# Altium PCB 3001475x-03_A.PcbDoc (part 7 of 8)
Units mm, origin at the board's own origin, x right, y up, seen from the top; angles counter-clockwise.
Board outline 100 x 72 mm, 12 copper layers (Top Layer, L2 GND, Layer 3, L4 GND, Layer 5, L6 PWR, L7 3V3, Layer 8, L9 GND, Layer 10, L11 GND, Bottom Layer), stack 1.735 mm thick; 428 components, 499 nets, 1973 pads, 1473 vias.
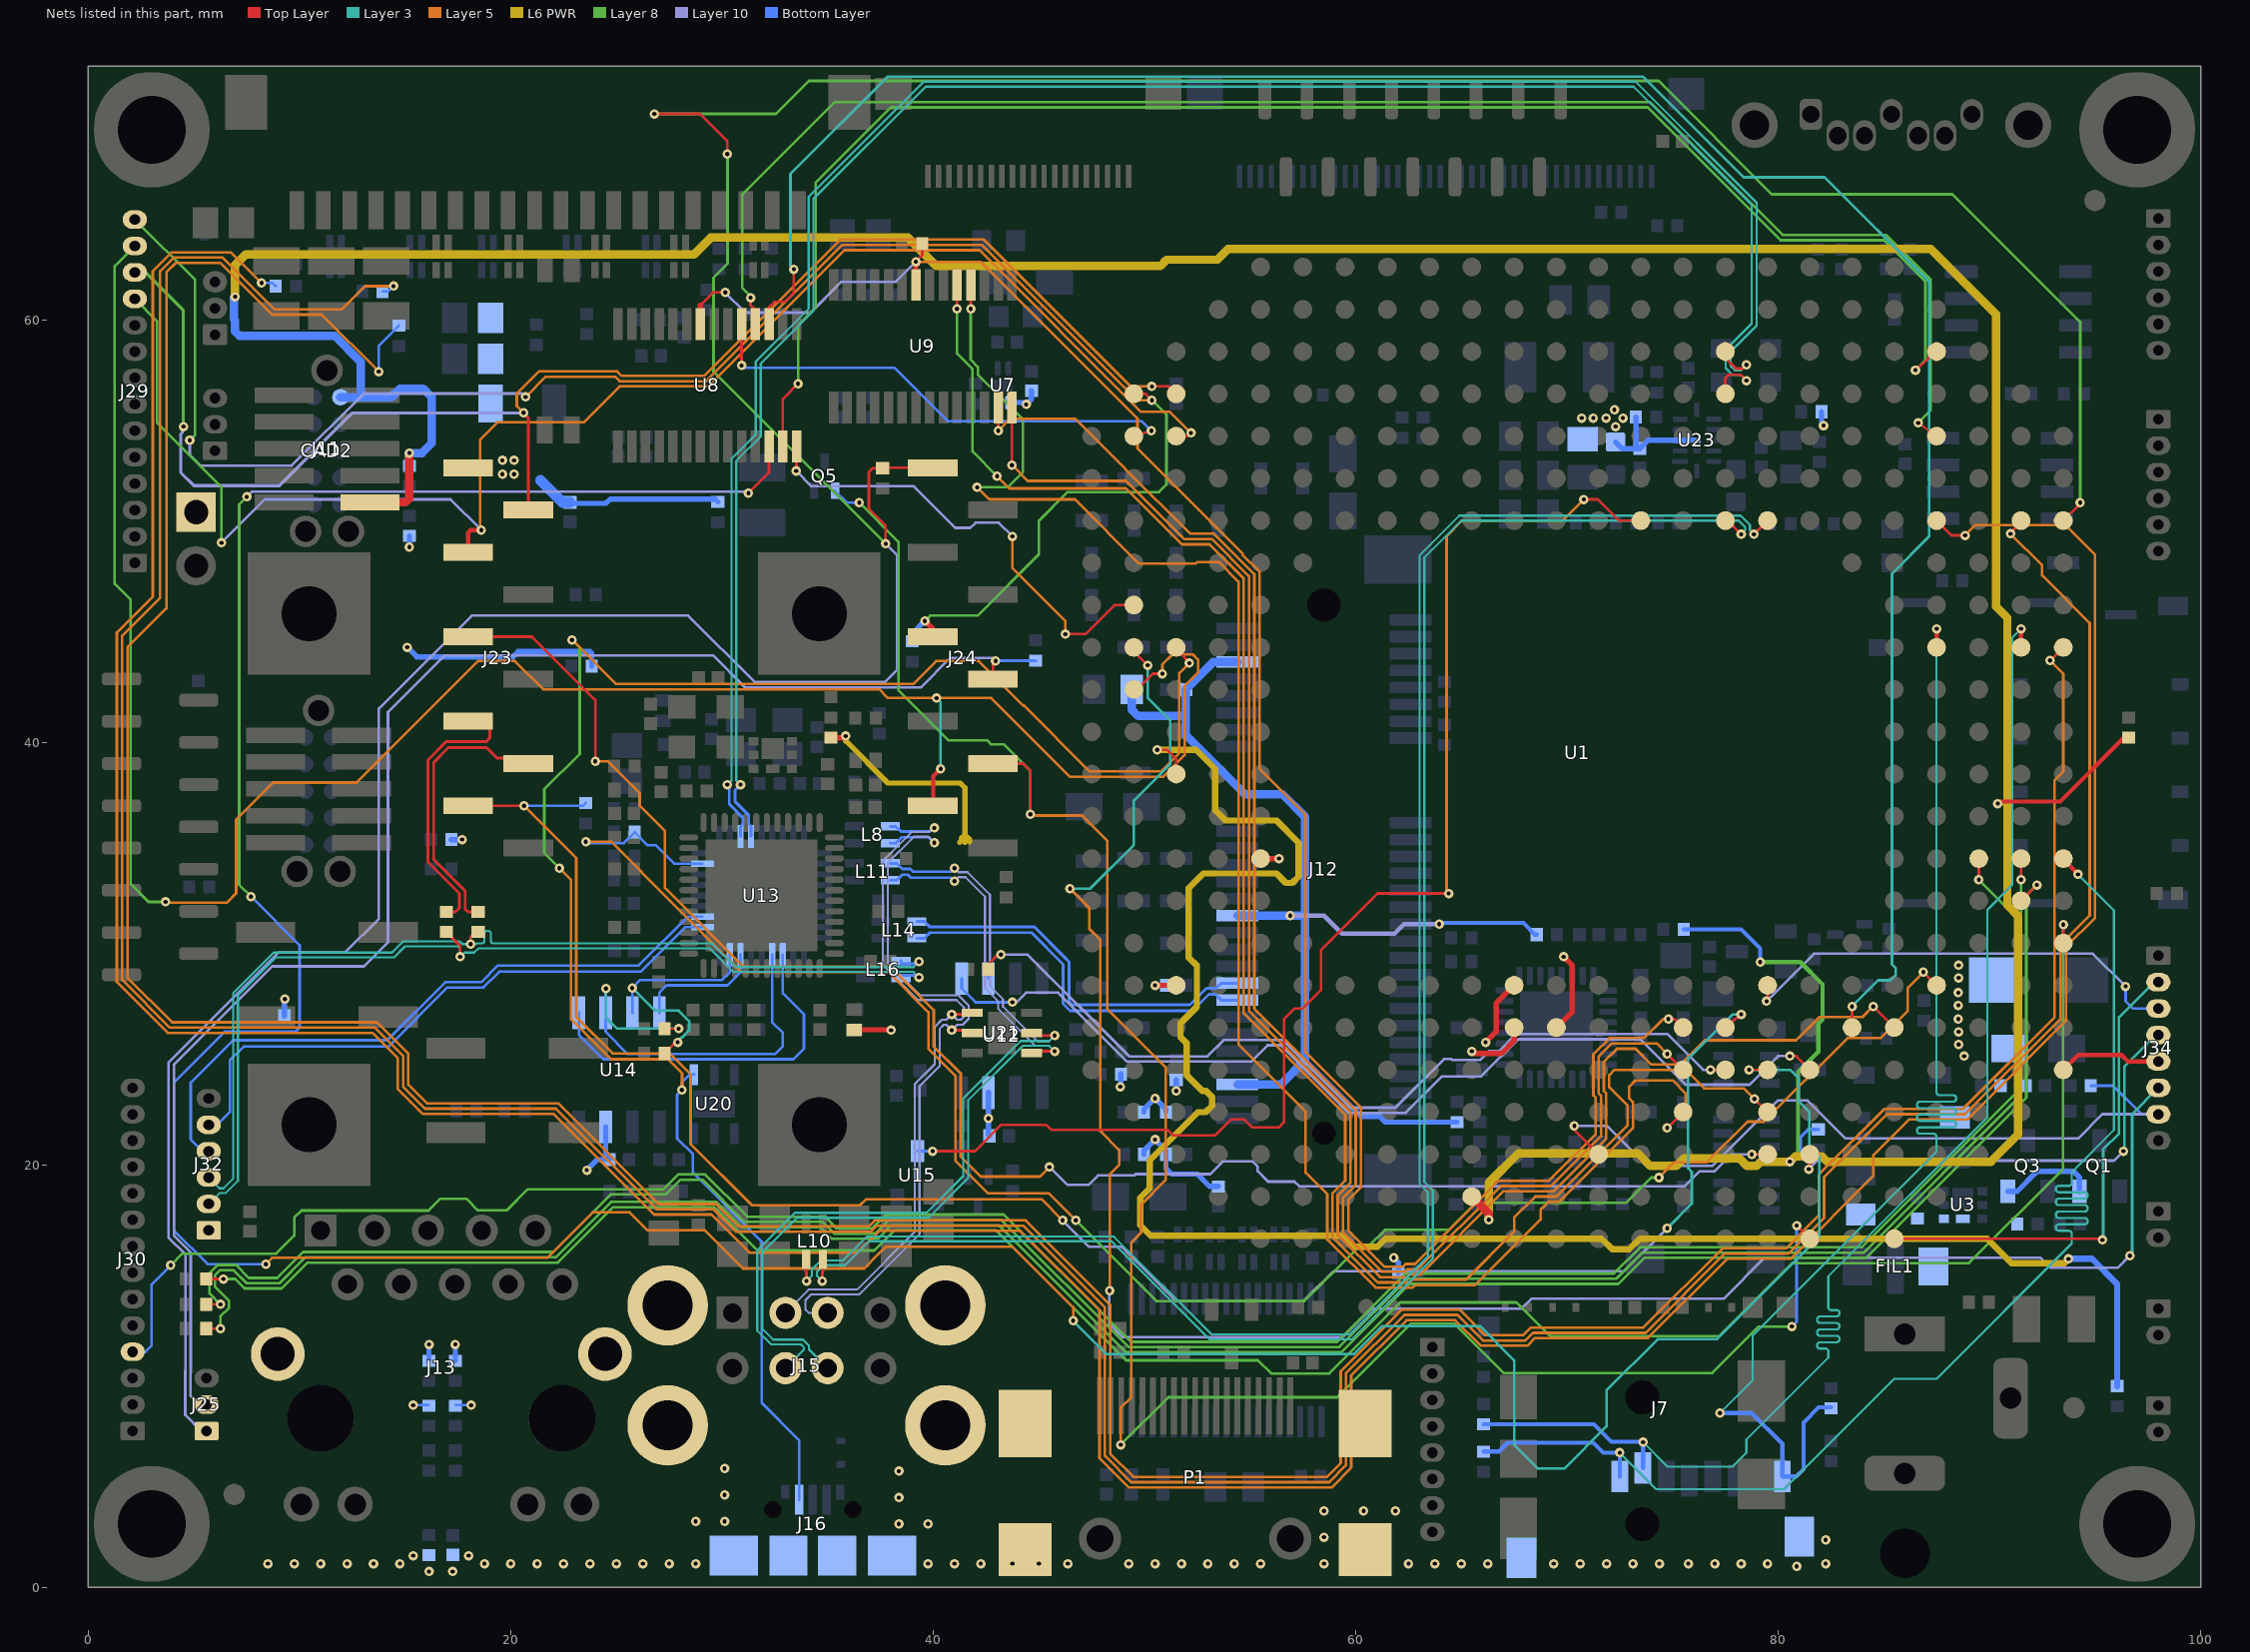
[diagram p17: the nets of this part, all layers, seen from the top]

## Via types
v1: diameter 0.45, hole 0.2, Top Layer to Bottom Layer, 1473 vias

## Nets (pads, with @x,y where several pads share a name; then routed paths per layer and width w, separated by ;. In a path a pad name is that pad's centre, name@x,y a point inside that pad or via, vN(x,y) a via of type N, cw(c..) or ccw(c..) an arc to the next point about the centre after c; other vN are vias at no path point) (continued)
SD2_DAT1: J7.8 R33.1 U1.K21 | length 62.6
  Top Layer w0.2: U1.K21@87.5,44.5 v1(87.5,45.375)
  Layer 3 w0.103: v1(77.25,8.25) 78.8,9.8 78.8,11.925 87.5,20.625 87.5,21.337 ccw(c87.363,21.337) 87.363,21.474 86.711,21.474 cw(c86.711,21.611) 86.574,21.611 86.574,21.641 cw(c86.711,21.641) 86.711,21.778 88.289,21.778 ccw(c88.289,21.915) 88.426,21.915 88.426,21.945 ccw(c88.289,21.945) 88.289,22.082 86.711,22.082 cw(c86.711,22.219) 86.574,22.219 86.574,22.249 cw(c86.711,22.249) 86.711,22.386 88.289,22.386 ccw(c88.289,22.523) 88.426,22.523 88.426,22.553 ccw(c88.289,22.553) 88.289,22.69 86.711,22.69 cw(c86.711,22.827) 86.574,22.827 86.574,22.857 cw(c86.711,22.857) 86.711,22.994 88.289,22.994 ccw(c88.289,23.131) 88.426,23.131 88.426,23.161 ccw(c88.289,23.161) 88.289,23.298 87.637,23.298 cw(c87.637,23.435) 87.5,23.435 v1(87.5,45.375)
  Bottom Layer w0.2: v1(77.25,8.25) 78.75,8.25 80.2,6.8 J7.8@80.2,5.25 80.85,5.25 81.2,5.6 81.2,7.8 81.92,8.52 R33.1@82.5,8.52
SD2_DAT2: J7.1 R32.1 U1.R24 | length 64.5
  Top Layer w0.2: U1.R24@93.5,34.5 v1(94.2,33.75)
  Layer 3 w0.103: v1(72.5,6.375) 74.225,4.65 80.275,4.65 85.5,9.875 87.5,9.875 93.9,16.275 93.9,16.744 ccw(c93.763,16.744) 93.763,16.881 93.288,16.881 cw(c93.288,17.018) 93.151,17.018 93.151,17.048 cw(c93.288,17.048) 93.288,17.185 94.512,17.185 ccw(c94.512,17.322) 94.649,17.322 94.649,17.352 ccw(c94.512,17.352) 94.512,17.489 93.288,17.489 cw(c93.288,17.626) 93.151,17.626 93.151,17.656 cw(c93.288,17.656) 93.288,17.793 94.512,17.793 ccw(c94.512,17.93) 94.649,17.93 94.649,17.96 ccw(c94.512,17.96) 94.512,18.097 93.288,18.097 cw(c93.288,18.234) 93.151,18.234 93.151,18.264 cw(c93.288,18.264) 93.288,18.401 94.512,18.401 ccw(c94.512,18.538) 94.649,18.538 94.649,18.568 ccw(c94.512,18.568) 94.512,18.705 93.288,18.705 cw(c93.288,18.842) 93.151,18.842 93.151,18.872 cw(c93.288,18.872) 93.288,19.009 93.763,19.009 ccw(c93.763,19.146) 93.9,19.146 93.9,19.65 95.9,21.65 95.9,32.05 v1(94.2,33.75)
  Bottom Layer w0.2: R32.1@66.05,6.43 66.78,6.43 67.2,6.85 71.25,6.85 71.725,6.375 v1(72.5,6.375) J7.1@72.5,5.25
SD2_DAT3: J7.2 R31.1 U1.K23 | length 65.5
  Top Layer w0.2: U1.K23@91.5,44.5 v1(91.5,45.375)
  Layer 3 w0.103: v1(73.6,6.875) 74.763,5.712 77.837,5.712 78.5,6.375 78.5,7 82.375,10.875 82.375,11.165 ccw(c82.238,11.165) 82.238,11.302 81.985,11.302 cw(c81.985,11.439) 81.849,11.439 81.849,11.469 cw(c81.985,11.469) 81.985,11.606 82.765,11.606 ccw(c82.765,11.743) 82.901,11.743 82.901,11.773 ccw(c82.765,11.773) 82.765,11.91 81.985,11.91 cw(c81.985,12.047) 81.849,12.047 81.849,12.077 cw(c81.985,12.077) 81.985,12.214 82.765,12.214 ccw(c82.765,12.351) 82.901,12.351 82.901,12.381 ccw(c82.765,12.381) 82.765,12.518 81.985,12.518 cw(c81.985,12.655) 81.849,12.655 81.849,12.685 cw(c81.985,12.685) 81.985,12.822 82.765,12.822 ccw(c82.765,12.959) 82.901,12.959 82.901,12.989 ccw(c82.765,12.989) 82.765,13.126 82.512,13.126 cw(c82.512,13.263) 82.375,13.263 82.375,14.725 89.9,22.25 89.9,32.071 91.079,33.25 91.079,44.954 v1(91.5,45.375)
  Bottom Layer w0.2: R31.1@66.05,7.72 71.28,7.72 72.1,6.9 73.575,6.9 v1(73.6,6.875) J7.2@73.6,5.65
SHLD: C33.1 J7.11 J7.12 J13.SHLD1 J13.SHLD2 J15.SH1 J15.SH2 J15.SH3 J15.SH4 J16.6 J16.7 J16.8 J16.9 P1.M1 P1.M2 P1.M3 P1.M4 R46.2
  other v1: 16.125,0.75 17.25,0.75 80.875,1 8.5,1.125 9.75,1.125 11,1.125 12.25,1.125 13.5,1.125 14.75,1.125 18.75,1.125 20,1.125 21.25,1.125 22.5,1.125 23.75,1.125 25,1.125 26.25,1.125 27.5,1.125 28.75,1.125 39.75,1.125 41,1.125 42.25,1.125 43.75,1.125 45,1.125 46.375,1.125 49.25,1.125 50.5,1.125 51.75,1.125 53,1.125 54.25,1.125 55.5,1.125 58.5,1.125 62.5,1.125 63.75,1.125 65,1.125 66.25,1.125 69.375,1.125 70.625,1.125 71.875,1.125 73.125,1.125 74.375,1.125 75.75,1.125 77,1.125 78.25,1.125 79.5,1.125 82.25,1.125 15.375,1.5 18,1.5 82.25,2.25 58.5,2.375 38.375,3 39.75,3 28.75,3.125 30.125,3.125 58.5,3.625 60.375,3.625 61.875,3.625 38.375,4.25 30.125,4.375 38.375,5.5 30.125,5.625
SPI1_CLK: J34.2 U1.AD20 | length 23.3
  Top Layer w0.125: U1.AD20@85.5,16.5 95.3,16.5 v1(95.35,16.45)
  Layer 3 w0.125: v1(95.35,16.45) 95.39,16.49 95.39,20.74 96.14,21.49 96.14,26.99 97.8,28.65 J34.2@98,28.65
SPI1_IRQ_N: J34.7 R122.2 U1.AB13 | length 36.5
  Top Layer w0.125: v1(70.35,21.85) 70.35,21.65 U1.AB13@71.5,20.5
  Layer 10 w0.125: v1(70.35,21.85) 71.9,21.85 73.8,19.95 76.883,19.95 79.983,23.05 81.4,23.05 83.2,21.25 94.2,21.25 95.35,22.4 J34.7@98,22.4
  Bottom Layer w0.125: R122.2@94.8,23.75 95.85,23.75 97.2,22.4 J34.7@98,22.4
SPI1_MISO: J34.3 U1.V17 | length 21.7
  Top Layer w0.125: v1(79.45,27.75) 79.5,27.8 U1.V17@79.5,28.5
  Layer 10 w0.125: v1(79.45,27.75) 81.7,30 94.9,30 v1(96.45,28.45)
  Bottom Layer w0.125: v1(96.45,28.45) 96.45,27.75 96.8,27.4 J34.3@98,27.4
SPI1_MOSI: J34.4 U1.AB18 | length 22.2
  Top Layer w0.125: v1(81.45,19.8) 81.5,19.85 U1.AB18@81.5,20.5
  Layer 10 w0.125: v1(81.45,19.8) 81.85,20.2 95.9,20.2 v1(96.35,20.65)
  Layer 3 w0.125: v1(96.35,20.65) 96.39,20.69 96.39,24.64 97.9,26.15 J34.4@98,26.15
SPI1_SS0: J34.5 U1.Y24 | length 4.9
  Top Layer w0.2: U1.Y24@93.5,24.5 94.2,25.2 96.25,25.2 96.55,24.9 J34.5@98,24.9
SPI1_SS1: J34.6 U1.K2 | length 95.5
  Top Layer w0.125: U1.K2@49.5,44.5 49.5,44.3 v1(50.15,43.65)
  Layer 5 w0.125: v1(46.475,33.075) 47.387,32.163 47.387,31.179 47.913,30.654 47.913,21.587 48.8,20.7 48.8,20 48.35,19.55 v1(48.35,14.05)
  Layer 10 w0.125: v1(48.35,14.05) 48.337,14.037 48.337,12.463 48.95,11.85 59.4,11.85 60.75,13.2 67.854,13.2 68.316,13.663 77.413,13.663 79.363,15.613 92.421,15.613 92.896,15.137 96.087,15.137 v1(96.65,15.7)
  Layer 3 w0.125: v1(46.475,33.075) 47.425,33.075 49.5,35.15 49.5,37.254 51.225,38.979 51.225,41.042 50.15,42.117 v1(50.15,43.65) ; v1(96.65,15.7) 96.763,15.813 96.763,22.413 J34.6@98,23.65
TOUCH_X1: R257.1 U1.T23 | length 111.2
  Top Layer w0.125: R257.1@5.58,12.25 v1(6.25,12.25) ; U1.T23@91.5,32.5 v1(92.25,33.25)
  Layer 8 w0.125: v1(6.25,12.25) 6.25,12.817 6.663,13.229 6.663,13.571 5.987,14.246 5.987,14.771 6.229,15.013 6.884,15.013 7.496,14.4 9.046,14.4 10.271,15.625 22.125,15.625 24.75,18.25 29.729,18.25 30.929,17.05 34.658,17.05 35.208,16.5 37.375,16.5 38.025,17.15 43.1,17.15 49.125,11.125 59.323,11.125 62.56,14.363 72.437,14.363 73.675,15.6 84.161,15.6 91.75,23.189 91.75,32.75 v1(92.25,33.25)
TOUCH_X2: R258.1 U1.R23 | length 110.4
  Top Layer w0.125: R258.1@5.58,13.4 v1(6.25,13.4) ; v1(91.5,33.5) U1.R23@91.5,34.5
  Layer 8 w0.125: v1(6.25,13.4) 5.737,13.913 5.737,14.874 6.126,15.263 6.987,15.263 7.6,14.65 8.943,14.65 10.168,15.875 11.279,15.875 22,15.875 24.725,18.6 27.329,18.6 28.029,19.3 29.075,19.3 31.075,17.3 34.762,17.3 35.312,16.75 37.25,16.75 37.9,17.4 43.225,17.4 49.25,11.375 59.219,11.375 62.457,14.613 72.334,14.613 73.571,15.85 84.057,15.85 91.5,23.293 v1(91.5,33.5)
TOUCH_Y1: R259.1 U1.U24 | length 111.5
  Top Layer w0.125: R259.1@5.58,14.6 v1(6.4,14.6) ; U1.U24@93.5,30.5 v1(93.5,31.375)
  Layer 8 w0.125: v1(6.4,14.6) 6.943,14.6 7.393,14.15 9.15,14.15 10.375,15.375 22.229,15.375 24.854,18 29.625,18 31.675,15.95 37.2,15.95 38.15,16.9 42.975,16.9 49.125,10.75 55.375,10.75 56,10.125 58.75,10.125 62.112,13.487 67.613,13.487 69.2,11.9 77.214,11.9 80.664,15.35 89.039,15.35 93.487,19.798 93.487,31.362 v1(93.5,31.375)
TOUCH_Y2: J30.4 U1.R22 | length 115.8
  Top Layer w0.125: v1(89.5,33.5) U1.R22@89.5,34.5
  Layer 8 w0.125: v1(3.9,15.25) 4.45,15.8 8.9,15.8 9.75,16.65 9.75,17.5 10.09,17.84 16.106,17.84 16.654,18.388 17.912,18.388 18.45,17.85 19.8,17.85 20.8,18.85 27.225,18.85 27.925,19.55 29.2,19.55 31.2,17.55 34.865,17.55 35.415,17 37.125,17 37.775,17.65 43.329,17.65 49.354,11.625 59.115,11.625 62.353,14.863 72.23,14.863 73.468,16.1 83.954,16.1 91.25,23.396 91.25,31.75 v1(89.5,33.5)
  Bottom Layer w0.125: J30.4@2.1,11.15 2.7,11.15 3,11.45 3,14.35 v1(3.9,15.25)
UART1_CTS_N: U1.Y17 U8.12 | length 173.1
  Top Layer w0.125: v1(31.25,51.8) 32.225,52.775 U8.12@32.225,54.005 ; v1(78.625,24.5) U1.Y17@79.5,24.5
  Layer 8 w0.125: v1(7.5,51.625) 7.137,51.262 7.137,33.263 v1(7.7,32.7)
  Layer 5 w0.125: v1(8.4,15.3) 8.7,15.6 21.725,15.6 23.875,17.75 25.632,17.75 26.482,16.9 29.186,16.9 30.986,15.1 36.728,15.1 37.378,15.75 37.753,16.125 43.75,16.125 46.625,13.25 v1(46.625,12.625)
  Layer 10 w0.125: v1(7.5,51.625) 7.75,51.875 31.175,51.875 v1(31.25,51.8)
  Layer 3 w0.125: v1(46.625,12.625) 48.212,11.038 59.913,11.038 61.25,12.375 65.875,12.375 67.5,10.75 67.5,6.75 68.625,5.625 69.875,5.625 71.875,7.625 71.875,9.325 74.3,11.75 77.1,11.75 81.95,16.6 81.95,20.4 81.475,20.875 81.475,22.525 80.975,23.025 80.975,24.1 80.575,24.5 v1(78.625,24.5)
  Bottom Layer w0.125: v1(7.7,32.7) 10,30.4 10,26.5 9.8,26.3 6.45,26.3 4.05,23.9 4.05,16.9 5.65,15.3 v1(8.4,15.3)
UART1_RTS_N: U1.W19 U8.17 | length 105.1
  Top Layer w0.125: U8.17@32.225,59.805 32.225,60.603 32.472,60.85 32.95,60.85 33.4,61.3 v1(33.4,62.4) ; U1.W19@83.5,26.5 v1(83.5,27.5)
  Layer 3 w0.125: v1(33.4,62.4) 33.237,62.563 33.237,66.912 37.837,71.512 73.613,71.512 78.375,66.75 82.2,66.75 87.15,61.8 87.15,49.75 85.387,47.987 85.387,29.496 85.563,29.321 85.563,28.979 85.321,28.737 84.737,28.737 v1(83.5,27.5)
UART1_RX: U1.E21 U8.18 | length 76.2
  Top Layer w0.125: v1(31.35,61.05) 31.35,60.7 31.575,60.475 U8.18@31.575,59.805 ; v1(86.625,55.125) U1.E21@87.5,54.5
  Layer 8 w0.125: v1(31.35,61.05) 31.417,61.05 30.95,61.517 30.95,65.925 35.338,70.313 73.924,70.313 80.213,64.024 85.104,64.024 87.225,61.904 87.225,55.725 v1(86.625,55.125)
UART1_TX: U1.C21 U8.13 | length 76.3
  Top Layer w0.125: U8.13@32.875,54.005 32.875,56.255 v1(33.6,56.98) ; v1(86.5,57.625) U1.C21@87.5,58.5
  Layer 8 w0.125: v1(33.6,56.98) 33.6,59.75 34.426,60.576 34.426,66.489 38,70.063 73.821,70.063 80.109,63.774 85.001,63.774 86.975,61.8 86.975,58.1 v1(86.5,57.625)
UART3_CTS_N: U1.Y15 U9.13 | length 74.2
  Top Layer w0.125: v1(43.075,54.75) U9.13@43.075,55.85 ; v1(74.75,25.25) U1.Y15@75.5,24.5
  Layer 5 w0.125: v1(43.075,54.75) 43.65,55.325 46.725,55.325 49.087,52.963 49.087,52.954 52.167,49.875 53.288,49.875 55.2,47.963 55.2,27.396 60,22.596 60,19.043 59.4,18.443 59.4,16.788 61.251,14.937 62.341,14.937 62.466,15.063 62.938,15.063 66.875,19 69.25,19 71.613,21.363 71.613,23.283 71.5,23.396 71.5,25.125 72.125,25.75 74.25,25.75 v1(74.75,25.25)
UART3_RTS_N: U1.AA15 U9.18 | length 86.5
  Top Layer w0.125: v1(41.775,60.525) U9.18@41.775,61.65 ; v1(74.75,21.75) U1.AA15@75.5,22.5
  Layer 8 w0.125: v1(41.775,60.525) 41.775,58.112 42.113,57.774 42.113,57.412 44.25,55.275 44.25,52.8 43.525,52.075 v1(42.075,52.075)
  Layer 5 w0.125: v1(42.075,52.075) 42.65,51.5 46.708,51.5 49.746,48.462 52.421,48.462 52.496,48.538 53.524,48.538 54.45,47.612 54.45,25.704 57.625,22.529 57.625,19.636 58.65,18.611 58.65,16.477 60.94,14.187 62.704,14.187 62.829,14.313 65.646,14.313 68.75,17.417 68.75,17.875 69.125,18.25 69.625,18.25 73.125,21.75 73.125,22.975 72.95,23.15 72.95,23.7 73.25,24 75,24 75.625,23.375 75.625,22.625 v1(74.75,21.75)
UART3_RX: U1.AA17 U9.19 | length 86.4
  Top Layer w0.125: v1(41.125,60.525) U9.19@41.125,61.65 ; v1(78.875,23.125) U1.AA17@79.5,22.5
  Layer 8 w0.125: v1(41.125,60.525) 41.125,58.408 41.863,57.671 41.863,53.762 v1(43.025,52.6)
  Layer 5 w0.125: v1(43.025,52.6) 43.6,52.025 49.125,52.025 51.775,49.375 53.081,49.375 54.7,47.756 54.7,27.175 59.5,22.375 59.5,19.25 58.9,18.65 58.9,16.581 61.043,14.437 62.548,14.437 62.673,14.563 65.213,14.563 67.5,16.85 67.5,17.5 68.5,18.5 69.5,18.5 72.875,21.875 72.875,22.8 72,23.675 72,24.25 72.25,24.5 75.625,24.5 76.5,23.625 78.375,23.625 v1(78.875,23.125)
UART3_TX: U1.W20 U9.14 | length 85.5
  Top Layer w0.125: v1(43.725,53.125) U9.14@43.725,55.85 U9.14@43.725,56 ; v1(84.5,27.5) U1.W20@85.5,26.5
  Layer 5 w0.125: v1(43.725,53.125) 44.475,52.375 49.129,52.375 51.879,49.625 53.185,49.625 54.95,47.86 54.95,27.293 59.75,22.493 59.75,19.146 59.15,18.546 59.15,16.685 61.147,14.687 62.445,14.687 62.57,14.813 63.063,14.813 67,18.75 69.375,18.75 71.863,21.238 71.863,23.387 71.75,23.499 71.75,24.875 72.375,25.5 73.25,25.5 74,24.75 75.375,24.75 76.525,25.9 80.85,25.9 81.95,27 84,27 v1(84.5,27.5)
UART4_RX: U1.E2 U8.19 | length 23.5
  Top Layer w0.125: v1(30.925,57.842) U8.19@30.925,59.805 ; U1.E2@49.5,54.5 v1(50.325,54.75)
  Bottom Layer w0.125: v1(30.925,57.842) 31.042,57.725 38.175,57.725 40.7,55.2 49.875,55.2 v1(50.325,54.75)
UART4_TX: U1.J2 U8.14 | length 22.4
  Top Layer w0.125: v1(33.512,52.85) 33.525,52.863 U8.14@33.525,54.005 U8.14@33.512,53.992 ; v1(46.25,45.125) 47.2,45.125 48.575,46.5 U1.J2@49.5,46.5
  Layer 5 w0.125: v1(43.75,49.75) 43.75,48.25 46.25,45.75 v1(46.25,45.125)
  Layer 10 w0.125: v1(33.512,52.85) 34.237,52.125 39.076,52.125 41.049,50.152 41.751,50.152 42,50.401 43.099,50.401 v1(43.75,49.75)
UART5_CTS_N: J24.5 J29.14 R145.2 U1.D2 | length 88.3
  Top Layer w0.125: U1.D2@49.5,56.5 50.05,56.5 v1(50.35,56.2)
  Top Layer w0.25: v1(39.6,45.75) 39.975,45.375 J24.5@39.975,45
  Layer 8 w0.125: J29.14@2.2,64.75 5.05,61.9 5.05,54.55 v1(4.8,54.3) ; v1(39.6,45.75) 39.85,46 42.1,46 45,48.9 45,50.496 46.354,51.85 50.683,51.85 51.038,52.204 51.038,55.512 v1(50.35,56.2)
  Layer 5 w0.125: v1(20.7,56.35) 21.663,57.313 24.934,57.313 25.146,57.1 29.246,57.1 35.696,63.55 42.296,63.55 49.646,56.2 v1(50.35,56.2)
  Layer 10 w0.125: v1(4.8,54.3) 4.8,53.6 5.3,53.1 9.629,53.1 13.041,56.513 20.537,56.513 v1(20.7,56.35)
  Bottom Layer w0.25: R145.2@39,44.78 39,45.15 v1(39.6,45.75)
UART5_RTS_N: J24.9 J29.13 U1.L2 | length 104.9
  Top Layer w0.125: U1.L2@49.5,42.5 49.65,42.5 50.4,43.25 v1(50.85,43.25)
  Top Layer w0.2: J24.9@40,37 40,38.4 v1(40.35,38.75)
  Layer 8 w0.125: J29.13@2.2,63.5 1.25,62.55 1.25,47.5 2,46.75 2,33.3 2.85,32.45 v1(3.65,32.45)
  Layer 5 w0.125: v1(3.65,32.45) 3.687,32.413 6.55,32.413 7,32.863 7,36.35 8.75,38.1 12.7,38.1 18.45,43.85 20.2,43.85 21.537,42.513 37.437,42.513 37.85,42.1 v1(40.15,42.1) 42.75,42.1 46.487,38.363 50.866,38.363 51.9,39.396 51.9,42.662 52.538,43.3 52.538,43.921 52.296,44.163 51.313,44.163 50.85,43.7 v1(50.85,43.25)
  Layer 3 w0.125: v1(40.15,42.1) 40.35,41.9 v1(40.35,38.75)
UART5_RX: J23.2 J29.12 U1.D3 | length 71.9
  Top Layer w0.125: v1(50.35,56.85) 51.15,56.85 U1.D3@51.5,56.5
  Top Layer w0.15: v1(20.6,55.6) 20.825,55.375 J23.2@20.825,51
  Layer 8 w0.15: J29.12@2.2,62.25 2.704,62.25 4.5,60.454 v1(4.5,54.95)
  Layer 5 w0.125: v1(20.6,55.6) 20.287,55.913 20.287,56.521 21.329,57.563 25.037,57.563 25.25,57.35 29.142,57.35 35.592,63.8 42.4,63.8 49.35,56.85 v1(50.35,56.85)
  Layer 10 w0.15: v1(4.5,54.95) 4.45,54.9 4.45,54.676 4.375,54.601 4.375,52.775 5,52.15 9.05,52.15 12.5,55.6 v1(20.6,55.6)
UART5_TX: J23.3 J29.11 U1.E3 | length 74.6
  Top Layer w0.125: U1.E3@51.5,54.5 52.05,54.5 v1(52.2,54.65)
  Top Layer w0.2: J23.3@17.975,49 17.975,49.925 18.1,50.05 v1(18.6,50.05)
  Layer 8 w0.125: J29.11@2.2,61 3.25,59.95 3.25,55.15 6.3,52.1 v1(6.3,49.45)
  Layer 5 w0.125: v1(18.6,50.05) 18.552,50.098 18.552,54.335 19.367,55.15 23.45,55.15 25.15,56.85 29.349,56.85 30.85,58.35 33.295,60.796 35.799,63.3 42.193,63.3 49.843,55.65 51.2,55.65 v1(52.2,54.65)
  Layer 10 w0.125: v1(6.3,49.45) 8.35,51.5 17.15,51.5 v1(18.6,50.05)
UART_PWR_EN: R127.2 U1.W15 U8.22 U9.22 | length 95.4
  Top Layer w0.125: 28.975,60.7 29.575,61.3 v1(30.15,61.3) ; v1(39.175,62.75) 39.48,63.055 R127.2@39.48,63.6 ; v1(74.8,26.9) 75.1,26.9 U1.W15@75.5,26.5
  Top Layer w0.25: U8.22@28.975,59.805 28.975,60.7 ; U9.22@39.175,61.65 v1(39.175,62.75)
  Layer 5 w0.125: v1(39.175,62.75) 42.25,62.75 49.667,55.333 49.667,53.917 54.637,48.946 54.637,48.879 55.45,48.067 55.45,38.742 57.625,36.567 57.625,25.325 60.25,22.7 60.25,18.939 59.65,18.339 59.65,16.892 61.354,15.187 62.237,15.187 62.363,15.313 62.813,15.313 66.75,19.25 69.146,19.25 71.363,21.466 71.363,23.179 71.25,23.292 71.25,25.229 72.021,26 73.65,26 74.55,26.9 v1(74.8,26.9)
  Layer 10 w0.125: v1(30.15,61.3) 31.103,60.347 34.197,60.347 35.65,61.8 38.225,61.8 v1(39.175,62.75)
USB_HUB_RESET_N: R69.2 U1.V21 U13.26 | length 90.1
  Top Layer w0.125: v1(86.875,29.125) U1.V21@87.5,28.5
  Layer 8 w0.125: v1(46.75,17.375) 46.75,17.36 50.56,13.55 50.8,13.55 51.143,13.55 57.565,13.55 58.437,14.422 58.437,14.428 58.972,14.963 58.978,14.963 60.228,16.212 60.671,16.212 61.383,16.925 64.4,16.925 65.675,18.2 72.8,18.2 74,19.4 v1(74.35,19.4)
  Layer 5 w0.125: v1(23.55,35.3) 24.75,35.3 26.212,33.838 26.212,33.829 30.906,29.135 37.864,29.135 39.775,27.225 39.775,25.5 41.05,24.225 41.05,20.2 42.6,18.65 45.475,18.65 v1(46.75,17.375) ; v1(74.35,19.4) 75.075,20.125 76.625,20.125 78.55,22.05 79.325,22.05 83.275,26 84.85,26 86.138,27.288 86.138,28.387 v1(86.875,29.125)
  Bottom Layer w0.125: v1(23.55,35.3) 23.623,35.227 25.352,35.227 25.855,35.73 R69.2@25.855,35.75 26.48,35.125 26.875,35.125 27.75,34.25 U13.26@29.075,34.25
USB_OTG_D_N: L10.1 U1.G16 | length 85.7
  Top Layer w0.137: v1(34.75,14.5) 34.75,14.923 34.775,14.948 L10.1@34.775,15.525 ; U1.G16@77.5,50.5 77.6,50.5 v1(78.25,49.85)
  Layer 3 w0.103: v1(34.75,14.5) 34.49,14.759 34.49,14.95 34.79,15.25 35.827,15.25 36.963,16.387 48.437,16.387 53.081,11.742 59.819,11.742 59.846,11.769 63.648,15.572 63.648,18.802 63.25,19.2 63.25,48.75 65,50.5 78.134,50.5 78.434,50.2 78.434,50.034 v1(78.25,49.85)
USB_OTG_D_P: L10.4 U1.G17 | length 86.3
  Top Layer w0.137: L10.4@33.975,15.525 33.975,14.948 34,14.923 v1(34,14.5) ; v1(78.85,49.85) U1.G17@79.5,50.5
  Layer 3 w0.103: v1(34,14.5) 34.259,14.759 34.259,15.046 34.695,15.481 35.731,15.481 36.868,16.618 48.532,16.618 48.6,16.55 53.177,11.973 59.723,11.973 63.417,15.667 63.417,18.706 63.019,19.104 63.019,48.846 64.904,50.731 78.23,50.731 78.665,50.296 78.665,50.034 v1(78.85,49.85)
USB_OTG_ID: J16.4 U1.K3 U20.1 | length 87.4
  Top Layer w0.125: U1.K3@51.5,44.5 v1(52.125,43.75)
  Layer 8 w0.125: v1(22.3,34.05) 21.587,34.763 21.587,37.78 23.263,39.455 23.263,44.487 v1(22.9,44.85)
  Layer 5 w0.125: v1(22.3,34.05) 22.85,33.5 22.85,26.896 24.746,25 27.446,25 28.113,24.334 28.113,23.563 v1(28.1,23.55) ; v1(22.9,44.85) 24.987,42.763 39.046,42.763 40.131,43.848 42.152,43.848 44.262,41.738 44.296,41.738 47.408,38.625 50.775,38.625 51.65,39.5 51.65,43.275 v1(52.125,43.75)
  Bottom Layer w0.125: U20.1@28.675,24.275 28.475,24.275 28.113,23.913 28.113,23.563 v1(28.1,23.55) 27.875,23.325 27.875,21.25 28.625,20.5 28.625,19.625 31.875,16.375 31.875,8.75 33.65,6.975 J16.4@33.65,4.15
USB_OTG_OC: R64.1 U1.Y16 U12.2 | length 42.6
  Top Layer w0.125: R64.1@42.605,29.25 42.605,29.505 43.05,29.95 v1(43.2,29.95) ; v1(76.8,24.5) U1.Y16@77.5,24.5
  Layer 10 w0.125: v1(43.2,29.95) 44.467,29.95 49.279,25.137 52.987,25.137 53.763,25.913 56.546,25.913 59.746,22.712 61.879,22.712 64.179,25.013 64.521,25.013 64.571,24.962 65.896,24.962 66.333,25.4 66.8,25.4 67.6,26.2 74.75,26.2 76.45,24.5 v1(76.8,24.5)
  Bottom Layer w0.125: U12.2@42.615,28.825 42.615,29.515 43.05,29.95 v1(43.2,29.95)
USB_OTG_PWR: U1.Y18 U12.1 | length 47.2
  Top Layer w0.125: v1(80.55,25.15) 80.85,25.15 U1.Y18@81.5,24.5
  Layer 10 w0.125: v1(43.75,27.7) 43.95,27.7 44.4,28.15 45.913,28.15 49.176,24.887 55.054,24.887 55.829,25.663 56.442,25.663 59.642,22.462 62.366,22.462 64.091,24.187 65.941,24.187 67.704,25.95 73.467,25.95 75.617,23.8 78.65,23.8 80,25.15 v1(80.55,25.15)
  Bottom Layer w0.125: U12.1@41.345,28.825 41.345,28.355 42,27.7 v1(43.75,27.7)
USB_OTG_VBUS: U1.G14 U15.D | length 62.2
  Top Layer w0.125: v1(39.975,20.65) 41.975,20.65 43.225,21.9 45.35,21.9 45.6,21.65 51.1,21.65 51.35,21.4 53.35,21.4 54.1,22.15 54.725,22.15 55.1,21.775 56.35,21.775 56.6,22.025 56.6,26.9 57.1,27.4 57.475,27.4 58.35,28.275 58.35,30.15 61.05,32.85 v1(64.4,32.85) ; v1(70.8,51.5) 71.467,51.5 72.467,50.5 U1.G14@73.5,50.5
  Layer 5 w0.125: v1(64.4,32.85) 64.3,32.95 64.3,49.754 65.046,50.5 69.8,50.5 v1(70.8,51.5)
  Bottom Layer w0.125: U15.D@39.25,20.65 v1(39.975,20.65)
USBH1_D_N: J15.A2 L8.2 U21.1 | length 36
  Top Layer w0.137: v1@40.757,27.125 v1(40.875,27.125) U21.1@41.775,27.125
  Layer 10 w0.103: J15.A2@33,13 34.098,14.098 36.398,14.098 39.119,16.819 39.119,23.819 40.069,24.769 40.069,26.53 40.404,26.865 40.615,26.865 v1(40.875,27.125) 41.135,26.865 41.3,26.865 41.45,27.015 41.45,27.45 41.1,27.8 39.273,27.8 37.619,29.454 37.619,34.396 38.989,35.765 39.816,35.765 v1@40.05,36
  Bottom Layer w0.137: L8.2@37.975,36.025 38.225,36.025 38.46,35.79 39.84,35.79 v1@40.05,36
  other v1: 40.05,35.95
USBH1_D_P: J15.A3 L8.3 U21.2 | length 36
  Top Layer w0.137: v1(40.875,26.375) U21.2@41.725,26.375
  Layer 10 w0.103: J15.A3@35,13 34.1,13 33.95,13.15 33.95,13.6 34.217,13.867 36.494,13.867 36.627,14 39.35,16.723 39.35,23.723 40.3,24.673 40.3,26.434 40.5,26.634 40.616,26.634 v1(40.875,26.375) 41.134,26.634 41.396,26.634 41.681,26.92 41.681,27.546 41.196,28.031 39.369,28.031 37.85,29.55 37.85,34.3 39.084,35.534 39.766,35.534 v1@40,35.3
  Bottom Layer w0.137: L8.3@37.975,35.225 38.225,35.225 38.51,35.51 39.79,35.51 v1@40,35.3
  other v1: 40.05,35.25
USBH1_OC_N: R65.1 U13.13 U14.2 | length 21.3
  Top Layer w0.125: R65.1@27.28,26.45 v1(27.95,26.45)
  Layer 3 w0.125: v1(24.5,28.35) 24.5,26.99 25.04,26.45 v1(27.95,26.45)
  Bottom Layer w0.125: v1(24.5,28.35) 24.49,28.34 U14.2@24.49,27.2 24.49,26.3 25.54,25.25 32.5,25.25 32.875,25.625 32.875,26.25 32.375,26.75 U13.13@32.375,29.95
USBH1_PWR_EN: U13.12 U14.1 | length 17.2
  Bottom Layer w0.125: U14.1@23.22,27.2 23.22,26.155 24.375,25 33.375,25 33.875,25.5 33.875,27.125 32.875,28.125 U13.12@32.875,29.95
USBH2_D_N: J15.B2 L11.2 U21.5 | length 43.4
  Top Layer w0.137: U21.5@44.775,26.125 v1(45.75,26.125)
  Layer 10 w0.103: v1(41,34.05) 41.197,33.853 41.624,33.853 42.681,32.796 42.681,28.465 43.3,27.846 43.3,27.5 44.935,25.865 45.49,25.865 v1(45.75,26.125)
  Layer 3 w0.103: J15.B2@33,10.38 33.884,11.264 33.884,11.35 33.734,11.5 32.323,11.5 31.669,12.154 31.669,15.946 33.454,17.731 39.681,17.731 41.419,19.469 41.419,23.146 44.139,25.865 45.49,25.865 v1(45.75,26.125)
  Bottom Layer w0.137: L11.2@37.975,34.275 38.275,34.275 38.535,34.015 38.916,34.015 39.053,33.878 40.828,33.878 v1(41,34.05)
USBH2_D_P: J15.B3 L11.3 U21.4 | length 43
  Top Layer w0.137: U21.4@44.725,25.375 v1(45.75,25.375)
  Layer 10 w0.103: v1(41,33.425) 41.197,33.622 41.528,33.622 42.45,32.7 42.45,28.369 43.069,27.75 43.069,27.404 44.839,25.634 45.491,25.634 v1(45.75,25.375)
  Layer 3 w0.103: J15.B3@35,10.38 34.115,11.265 34.115,11.446 33.83,11.731 32.419,11.731 31.9,12.25 31.9,15.85 33.55,17.5 39.777,17.5 41.65,19.373 41.65,23.05 44.234,25.634 45.491,25.634 v1(45.75,25.375)
  Bottom Layer w0.137: L11.3@37.975,33.475 38.275,33.475 38.535,33.735 38.8,33.735 38.938,33.598 40.827,33.598 v1(41,33.425)
USBH2_OC_N: R66.1 U13.17 U14.3 | length 12.4
  Top Layer w0.125: R66.1@27.28,25.275 27.805,25.8 v1(27.9,25.8)
  Layer 3 w0.125: v1(25.75,28.375) 26.825,27.3 27.95,27.3 28.45,26.8 28.45,26.367 28.121,26.037 28.087,26.037 27.9,25.85 v1(27.9,25.8)
  Bottom Layer w0.125: U14.3@25.76,27.2 25.76,28.385 26.125,28.75 30,28.75 30.375,29.125 U13.17@30.375,29.95
USBH2_PWR_EN: U13.16 U14.4 | length 6
  Bottom Layer w0.125: U14.4@27.03,27.2 27.03,28.155 27.375,28.5 30.25,28.5 30.875,29.125 U13.16@30.875,29.95
USBH3_D_N: J12.36 L14.2 | length 18.3
  Bottom Layer w0.137: L14.2@39.225,31.525 39.575,31.525 39.825,31.275 44.771,31.275 46.255,29.791 46.43,29.616 46.43,27.747 46.597,27.58 52.155,27.58 52.93,28.355 53.38,28.355 53.625,28.6 J12.36@54.4,28.6
USBH3_D_P: J12.38 L14.3 | length 18.4
  Bottom Layer w0.137: L14.3@39.225,30.725 39.575,30.725 39.845,30.995 44.655,30.995 46.15,29.5 46.15,27.625 46.475,27.3 52.275,27.3 53.05,28.075 53.35,28.075 53.625,27.8 J12.38@54.4,27.8
USBH4_D_N: J32.3 L16.2 R129.1 | length 47.2
  Top Layer w0.137: v1(18.1,30.45) 18.1,30.8 18.32,31.02 R129.1@18.45,31.02
  Layer 3 w0.103: J32.3@5.7,19.4 6.209,18.89 6.4,18.89 6.85,19.34 6.85,28.127 8.773,30.05 14.373,30.05 14.83,30.507 14.898,30.574 17.589,30.574 17.657,30.507 17.713,30.45 v1(18.1,30.45) 18.345,30.45 18.376,30.481 18.6,30.481 18.615,30.481 ccw(c18.615,30.617) 18.751,30.617 18.751,30.945 cw(c18.888,30.945) 18.888,31.081 18.918,31.081 cw(c18.918,30.945) 19.054,30.945 19.054,30.617 ccw(c19.191,30.617) 19.191,30.481 19.357,30.481 19.4,30.481 29.519,30.481 30.635,29.365 39.065,29.365 v1(39.325,29.625)
  Bottom Layer w0.137: L16.2@38.475,29.65 38.475,29.525 39.225,29.525 v1(39.325,29.625)
USBH4_D_P: J32.2 L16.3 R102.1 | length 47.4
  Top Layer w0.137: R102.1@16.95,31.02 17.6,30.37 17.6,30.02 v1(17.6,29.85)
  Layer 3 w0.103: J32.2@5.7,18.15 6.209,18.659 6.496,18.659 7.081,19.245 7.081,28.031 8.869,29.819 14.469,29.819 14.993,30.343 17.493,30.343 17.6,30.237 v1(17.6,29.85) 17.795,30.045 18.268,30.045 18.472,30.25 29.423,30.25 30.539,29.134 39.065,29.134 v1(39.325,28.875)
  Bottom Layer w0.137: L16.3@38.475,28.85 38.475,28.975 39.225,28.975 v1(39.325,28.875)
USBH4_OC_N: J32.4 U13.21 | length 31.3
  Bottom Layer w0.125: J32.4@5.7,20.65 5.4,20.65 4.85,21.2 4.85,23.9 6.85,25.9 14.15,25.9 16.9,28.65 18.6,28.65 19.387,29.437 26.062,29.437 28.375,31.75 U13.21@29.075,31.75
USBH4_PWR_EN: J32.5 U13.20 | length 28.7
  Bottom Layer w0.125: J32.5@5.7,21.9 6.1,21.9 6.7,22.5 6.7,24.95 7.35,25.6 14.204,25.6 17.004,28.4 18.704,28.4 19.454,29.15 26.15,29.15 28.25,31.25 U13.20@29.075,31.25
USBH_D_N: U1.C16 U13.30 | length 92.5
  Top Layer w0.137: U1.C16@77.5,58.5 77.5,58.2 78,57.7 78.325,57.7 v1(78.5,57.875)
  Layer 3 w0.103: v1(30.25,38) 30.447,38.197 30.447,53.424 31.6,54.577 31.6,58.027 34.1,60.527 34.1,65.827 39.547,71.273 73.253,71.273 78.981,65.546 78.981,59.731 77.75,58.5 77.75,57.815 77.95,57.615 78.24,57.615 v1(78.5,57.875)
  Bottom Layer w0.137: v1(30.25,38) 30.342,37.908 30.342,37.077 30.985,36.434 30.985,36.135 30.875,36.025 U13.30@30.875,35.55
USBH_D_P: U1.D16 U13.31 | length 92.5
  Top Layer w0.137: U1.D16@77.5,56.5 77.5,57.238 77.663,57.4 78.225,57.4 v1(78.5,57.125)
  Layer 3 w0.103: v1(30.875,38) 30.678,38.197 30.678,53.328 31.831,54.481 31.831,57.931 34.331,60.431 34.331,65.731 39.642,71.042 73.158,71.042 78.75,65.45 78.75,59.827 77.519,58.596 77.519,57.72 77.854,57.384 78.241,57.384 v1(78.5,57.125)
  Bottom Layer w0.137: v1(30.875,38) 30.622,37.747 30.622,37.193 31.265,36.55 31.265,36.135 31.375,36.025 U13.31@31.375,35.55
USER_LED0: R121.2 U1.G21 | length 193.7
  Top Layer w0.125: U1.G21@87.5,50.5 88.2,49.8 v1(88.85,49.8)
  Layer 5 w0.125: v1(8.2,61.75) 6.75,63.2 3.943,63.2 3.05,62.307 3.05,46.9 1.35,45.2 1.35,28.657 3.757,26.25 13.457,26.25 14.65,25.057 14.65,23.593 15.83,22.413 22.03,22.413 26.793,17.65 29.496,17.65 31.296,15.85 36.418,15.85 37.155,16.587 37.443,16.875 44.125,16.875 47.875,13.125 47.875,6.354 47.875,6.118 49.263,4.73 58.855,4.73 59.788,5.663 59.788,10.027 62.411,12.65 64.714,12.65 65.927,11.437 68.134,11.437 68.496,11.8 73.832,11.8 77.582,15.55 80.59,15.55 84.5,19.46 84.5,20.45 86.2,22.15 88.95,22.15 93.625,26.825 93.625,30.325 95,31.7 95,48.875 93.587,50.288 89.338,50.288 v1(88.85,49.8)
  Bottom Layer w0.125: v1(8.2,61.75) 8.72,61.75 R121.2@8.87,61.6
USER_LED1: R120.2 U1.G23 | length 194.2
  Top Layer w0.125: v1(91,49.875) U1.G23@91.5,50.5
  Layer 5 w0.125: v1(14.45,61.6) 13.1,61.6 12,60.5 8.804,60.5 6.354,62.95 4.046,62.95 3.4,62.304 3.4,46.85 1.6,45.05 1.6,28.761 3.861,26.5 13.561,26.5 14.9,25.161 14.9,23.696 15.934,22.663 22.134,22.663 26.896,17.9 29.6,17.9 29.625,17.875 30.663,16.837 37.052,16.837 37.339,17.125 44.25,17.125 48.125,13.25 48.125,6.221 49.366,4.98 58.745,4.98 59.538,5.772 59.538,10.13 62.307,12.9 64.818,12.9 66.03,11.687 68.03,11.687 68.393,12.05 73.729,12.05 77.479,15.8 80.487,15.8 82.175,17.488 82.175,19.425 85.15,22.4 88.846,22.4 93.375,26.929 93.375,30.429 94.75,31.804 94.75,45.65 92.5,47.9 92.5,48.375 v1(91,49.875)
  Bottom Layer w0.125: R120.2@13.93,61.35 14.2,61.35 v1(14.45,61.6)
USER_LED2: R119.2 U1.K24 | length 187.3
  Top Layer w0.125: v1(92.875,43.875) U1.K24@93.5,44.5
  Layer 5 w0.125: v1(13.75,57.55) 11.05,60.25 8.7,60.25 6.25,62.7 4.15,62.7 3.7,62.25 3.7,46.35 1.85,44.5 1.85,28.864 3.964,26.75 13.664,26.75 15.15,25.264 15.15,23.8 16.037,22.913 22.237,22.913 27,18.15 29.725,18.15 30.788,17.087 36.948,17.087 37.236,17.375 44.375,17.375 48.375,13.375 48.375,6.325 49.47,5.23 58.642,5.23 59.288,5.876 59.288,10.234 62.204,13.15 64.921,13.15 66.134,11.937 67.927,11.937 68.289,12.3 73.625,12.3 77.375,16.05 80.383,16.05 81.925,17.592 81.925,19.529 82,19.604 82,19.625 85.025,22.65 88.743,22.65 93.087,26.995 93.087,38.212 93.5,38.625 93.5,43.25 v1(92.875,43.875)
  Bottom Layer w0.125: v1(13.75,57.55) 13.75,58.78 R119.2@14.7,59.73
VCC_LICELL: R8.2 U1.N3 | length 90.8
  Top Layer w0.125: v1(50.6,39.65) 51.067,39.65 51.5,39.217 U1.N3@51.5,38.5
  L6 PWR w0.3: v1(50.6,39.65) 52.45,39.65 53.35,38.75 53.35,36.8 53.85,36.3 56.25,36.3 57.3,35.25 57.3,33.65 57,33.35 56.693,33.35 56.243,33.8 52.793,33.8 52.1,33.107 52.1,29.817 52.48,29.437 52.48,27.487 51.7,26.707 51.7,26.057 52,25.757 52,25.3 52,24.243 52.743,23.5 52.907,23.5 53.2,23.207 53.2,22.793 52.907,22.5 52.543,22.5 50.25,20.207 50.25,18.9 49.8,18.45 49.8,17.143 50.293,16.65 59.425,16.65 59.95,16.125 61.025,16.125 61.4,16.5 71.65,16.5 72.15,16 72.95,16 73.45,16.5 89.9,16.5 91.05,15.35 93.55,15.35 v1(93.75,15.55)
  Bottom Layer w0.3: v1(93.75,15.55) 94.85,15.55 96.05,14.35 R8.2@96.05,9.53
VIN: FIL1.3 Q1.2 Q3.2 R6.1 R11.2 R126.2 U3.4 U3.8 | length 4.6
  Bottom Layer w0.25: Q3.2@90.87,18.75 91.32,18.75 92.27,19.7 93.97,19.7 94.27,19.4 Q1.2@94.27,18.75
VLDO3_MCA: CAD2.1 J11.1 R23.2 R80.1 R150.1 R153.2 U1.AC10 | length 207.2
  Top Layer w0.2: v1(90.4,37.1) 90.5,37.2 93.35,37.2 96.37,40.22 R80.1@96.6,40.22
  Top Layer w0.4: J11.1@13.332,51.36 15.01,51.36 15.2,51.55 v1(15.2,53.7) ; U1.AC10@65.5,18.5 66.3,17.7 v1(66.3,17.4)
  Layer 8 w0.2: v1(79.15,29.6) 81.05,29.6 82.1,28.55 82.1,26.886 81.9,26.686 81.9,25.35 80.95,24.4 80.95,20.55 v1(80.55,20.15)
  L6 PWR w0.2: v1(90.4,37.1) 90.85,37.1
  L6 PWR w0.4: v1(6.95,61.1) 6.95,62.6 7.45,63.1 28.672,63.1 29.472,63.9 38.803,63.9 40.153,62.55 50.75,62.55 51.05,62.85 53.453,62.85 53.953,63.35 87.228,63.35 90.325,60.253 90.325,46.425 90.85,45.9 90.85,37.1 90.85,32.3 91.35,31.8 91.35,21.425 90.075,20.15 82.322,20.15 82.072,20.4 80.803,20.4 80.553,20.15 v1(80.55,20.15) 79.178,20.15 78.978,19.95 78.522,19.95 78.172,20.3 75.522,20.3 75.172,19.95 73.95,19.95 73.35,20.55 67.7,20.55 66.3,19.15 v1(66.3,17.4)
  Bottom Layer w0.15: v1(80.55,20.15) 80.7,20.15 81.05,20.5 81.05,21.3 81.43,21.68 R153.2@81.9,21.68
  Bottom Layer w0.2: R23.2@75.53,31.15 78.25,31.15 79.15,30.25 v1(79.15,29.6)
  Bottom Layer w0.4: v1(6.95,61.1) 6.9,61.05 6.9,60.022 6.95,59.972 6.95,59.45 7.15,59.25 11.662,59.25 12.9,58.012 12.9,56.34 ; CAD2.1@11.935,56.34 12.9,56.34 ; R150.1@15.2,53.08 v1(15.2,53.7) 15.8,53.7 16.25,54.15 16.25,56.35 15.85,56.75 14.75,56.75 14.34,56.34 12.9,56.34
VLDO4_2V5: L3.2 R26.2 R38.2 R40.2 R41.2 R45.2 R53.2 R55.2 R58.2 R60.2 R61.2 R62.2 R63.2 R81.1 R154.1 U1.R5 U1.V3 | length 27
  Top Layer w0.25: R154.1@35.15,40.22 35.77,40.22 v1(35.85,40.3) ; L3.2@36.375,26.395 v1@38,26.395 ; v1(50.5,28.5) U1.V3@51.5,28.5 ; U1.R5@55.5,34.5 v1(56.375,34.5)
  L6 PWR w0.25: v1(35.85,40.3) 35.85,40.078 37.853,38.075 41.275,38.075 41.5,37.85 41.5,35.625 ; 41.25,35.275 41.325,35.35 41.325,35.45 41.5,35.625 ; 41.5,35.275 41.5,35.625 ; 41.725,35.3 41.725,35.4 41.5,35.625
  Bottom Layer w0.125: v1(15.375,8.625) R53.2@16.105,8.625 ; R55.2@17.395,8.625 v1(18.125,8.625)
  Bottom Layer w0.25: R45.2@16.125,10.73 v1(16.125,11.5) ; R38.2@17.375,10.73 v1(17.375,11.5) ; v1(48.85,23.7) 48.88,23.73 R26.2@48.88,24.3 ; R61.2@49.98,20.5 49.98,20.68 v1(50.5,21.2) 51.02,20.68 R63.2@51.02,20.5 51.02,19.83 51.287,19.563 52.5,19.563 53.083,18.98 R62.2@53.5,18.98 ; R60.2@49.98,22.5 49.98,22.63 v1(50.5,23.15) 51.02,22.63 R40.2@51.02,22.5 ; v1(50.5,28.5) R58.2@51.02,28.5 ; v1(51.5,23.5) R41.2@51.5,24.02 ; v1(61.8,15.6) 62.02,15.38 R81.1@62.02,14.9
  other v1: 38,26.375
VLDO6_1V5: C40.2 C41.2 J12.6 J12.28 J12.48 R82.1 R131.2 | length 55.3
  Layer 10 w0.2: v1(56.9,31.8) 58.5,31.8 59.35,30.95 61.837,30.95 62.287,31.4 v1(63.95,31.4)
  Bottom Layer w0.2: v1(63.95,31.4) 64,31.45 67.939,31.45 68.489,30.9 R131.2@68.57,30.9
  Bottom Layer w0.25: 57.6,24.95 60.25,22.3 61.122,22.3 61.402,22.02 R82.1@64.8,22.02
  Bottom Layer w0.4: C40.2@49.4,42.5 49.4,41.55 49.7,41.25 51.96,41.25 ; J12.48@54.4,23.8 56.45,23.8 57.6,24.95 57.6,31.8 ; J12.28@54.4,31.8 57.6,31.8 ; J12.6@54.4,43.8 53.25,43.8 51.96,42.51 C41.2@51.96,42.5 51.96,41.25 ; 51.96,41.25 51.96,40.34 54.75,37.55 56.528,37.55 57.6,36.478 57.6,31.8
VSYS: C1.1 C2.2 C3.2 C11.2 C62.2 C65.1 C111.2 C112.2 C113.2 J18.1 J32.1 R101.1 R137.2 R140.2 R147.2 R148.2 R151.1 R152.1 U1.V11 U1.W11 U1.W12 U5.K U7.3 U12.7 U14.7 U23.3 U23.14 | length 34.5
  Top Layer w0.254: v1(65.5,25.375) 65.602,25.273 66.898,25.273 67.5,25.875 U1.W11@67.5,26.5 ; v1(66.15,25.8) 66.65,26.3 66.65,27.65 U1.V11@67.5,28.5 ; U1.W12@69.5,26.5 70.25,27.25 70.25,29.45 v1(69.85,29.85)
  Bottom Layer w0.254: R147.2@9.28,27.05 9.28,27.83 v1(9.3,27.85) ; v1(15.1,44.5) 15.55,44.05 20.1,44.05 20.35,44.3 23.75,44.3 23.83,44.22 R101.1@23.83,43.6 ; v1(15.2,49.25) R152.1@15.2,49.77 ; R151.1@17.18,35.4 v1(17.7,35.4) ; v1(23.6,19.75) 24.1,20.25 C65.1@24.665,20.25 24.49,20.425 U14.7@24.49,21.8 ; U12.7@42.615,23.425 v1(42.615,22.2) 42.615,21.425 C62.2@42.665,21.375 ; U7.3@43.55,56.09 44.31,56.09 v1(44.4,56) 44.65,56.25 C11.2@44.65,56.64 ; C112.2@72.3,54.22 72.61,53.91 C113.2@73.45,53.91 ; R137.2@73.27,55.4 73.27,54.09 C113.2@73.45,53.91 ; U23.14@76.15,54.3 U23.3@75.35,54.3 73.84,54.3 C113.2@73.45,53.91 ; R140.2@82.056,55.65 82.056,55.094 v1(82.15,55)
  other v1: 88.8,25.15 88.55,25.7 88.55,26.3 88.53,26.9 88.53,27.55 88.53,28.15 88.55,28.85 88.55,29.45 72.3,54.95 70.7,55.35 71.25,55.35 71.85,55.35 72.65,55.35 72.25,55.75
XBEE_ASSOC: J24.6 J25.2 R134.1 | length 74.3
  Top Layer w0.125: J24.6@42.825,43 42.825,43.725 v1(42.95,43.85)
  Layer 10 w0.125: J25.2@5.6,8.65 5.25,8.65 4.837,9.063 4.837,10.159 4.85,10.171 4.85,15.854 4.05,16.654 4.05,24.746 8.704,29.4 13.05,29.4 14.187,30.537 14.187,41.437 16.863,44.113 29.587,44.113 31.1,42.6 39.4,42.6 40.8,44 42.8,44 v1(42.95,43.85)
  Bottom Layer w0.125: v1(42.95,43.85) 42.97,43.87 R134.1@44.85,43.87
XBEE_IDENT: J24.1 J25.1 R136.1 U1.G24 | length 191.3
  Top Layer w0.125: v1(26.8,69.75) 28.95,69.75 30.25,68.45 v1(30.25,67.85) ; v1(37.75,49.4) 37.75,50.25 36.95,51.05 36.95,52.8 37.13,52.98 R136.1@37.6,52.98 37.62,53 J24.1@39.975,53 ; U1.G24@93.5,50.5 94.3,51.3 v1(94.3,51.35)
  Layer 8 w0.125: v1(26.8,69.75) 32.55,69.75 34.113,71.313 74.339,71.313 79.701,65.95 88.25,65.95 94.3,59.9 v1(94.3,51.35) ; v1(30.25,67.85) 30.263,67.837 30.263,62.663 29.6,62 29.6,57.55 v1(37.75,49.4)
  Layer 10 w0.125: J25.1@5.6,7.4 5.35,7.4 4.587,8.163 4.587,10.262 4.6,10.275 4.6,15.75 3.8,16.55 3.8,24.85 9,30.05 12.15,30.05 13.75,31.65 13.75,41.6 18.15,46 28.4,46 31.55,42.85 37.7,42.85 38.3,43.45 38.3,48.85 v1(37.75,49.4)
XBEE_ON/SLEEP_N: J24.8 Q5.G U1.AD18 | length 101.4
  Top Layer w0.125: J24.8@42.825,39 44.25,39 44.6,38.65 v1(44.6,36.6) ; v1(80.875,17.125) U1.AD18@81.5,16.5
  Layer 8 w0.125: v1(36.5,51.35) 38.35,49.5 38.35,42.467 40.717,40.1 42.554,40.1 42.754,39.9 43.35,39.9 44.6,38.65 v1(44.6,36.6) ; v1(48.875,6.75) 51.125,9 59.125,9 62.612,12.487 64.666,12.487 67.004,10.15 76.879,10.15 79.079,12.35 v1(80.65,12.35)
  Layer 5 w0.125: v1(44.6,36.6) 44.663,36.537 47.046,36.537 48.237,35.346 48.237,27.388 51,24.625 51,19.274 49.837,18.111 49.837,16.787 49.375,16.325 49.375,9 48.875,8.5 v1(48.875,6.75)
  Bottom Layer w0.125: Q5.G@35.35,51.91 35.91,51.35 v1(36.5,51.35) ; v1(80.65,12.35) 80.875,12.575 v1(80.875,17.125)
XBEE_RESET_N: J23.5 U1.AB17 | length 81.3
  Top Layer w0.125: J23.5@17.975,45 21,45 24,42 v1(24,39.1) ; v1(78.75,20.5) U1.AB17@79.5,20.5
  Layer 5 w0.125: v1(24,39.1) 24.602,39.1 26.1,37.602 26.1,37 27.3,35.8 27.3,33.104 31.018,29.386 37.968,29.386 40.025,27.329 40.025,25.604 41.3,24.329 41.3,20.4 42.25,19.45 45.05,19.45 v1(45.5,19.9)
  Layer 10 w0.125: v1(45.5,19.9) 46.35,19.05 47.35,19.05 47.8,19.5 49.517,19.5 49.579,19.563 53.113,19.563 53.713,20.163 55.121,20.163 55.363,19.921 55.363,19.701 55.851,19.212 57.099,19.212 57.324,18.987 75.571,18.987 76.283,19.7 76.987,19.7 77.787,20.5 v1(78.75,20.5)
XBEE_SLEEP_RQ: J23.9 R146.2 U1.W16 | length 90.4
  Top Layer w0.125: J23.9@17.975,37 v1@20.575,37 ; U1.W16@77.5,26.5 v1(78.25,27.125)
  Layer 5 w0.125: v1(20.625,37) 23.1,34.525 23.1,27 24.825,25.275 27.525,25.275 28.513,24.287 28.513,20.987 31.413,18.087 36.534,18.087 36.821,18.375 45.125,18.375 v1(46.125,17.375)
  Layer 10 w0.125: v1(46.125,17.375) 47.375,16.125 48.925,16.125 51.5,13.55 57.529,13.55 58.929,14.95 58.96,14.95 58.972,14.963 72.705,14.963 74.743,17 v1(74.75,17)
  Layer 3 w0.125: v1(74.75,17) 75.913,18.163 75.913,19.671 75.737,19.846 75.737,25.021 77.842,27.125 v1(78.25,27.125)
  Bottom Layer w0.125: v1(20.625,37) 23.42,37 R146.2@23.55,37.13
XBEE_USB_N: J23.8 R129.2 | length 13.3
  Top Layer w0.137: R129.2@18.45,31.98 17.97,31.98 17.84,32.11 17.84,32.45 17.84,32.966 16.35,34.456 16.35,39.05 17.05,39.75 18.85,39.75 19.35,39.25 20.575,39.25 J23.8@20.825,39
XBEE_USB_P: J23.7 R102.2 | length 13.6
  Top Layer w0.137: R102.2@16.95,31.98 17.38,31.98 17.56,32.16 17.56,32.85 16.07,34.34 16.07,39.166 16.934,40.03 18.83,40.03 19,40.2 19,40.95 19.05,41 J23.7@17.975,41
XBEE_VCC: C101.2 C114.2 J23.1 L28.2 L29.2 R133.1 | length 9
  Bottom Layer w0.25: C101.2@22.8,51.36 22.847,51.313 24.5,51.313 24.702,51.515 29.665,51.515 R133.1@29.8,51.38
  Bottom Layer w0.5: 21.4,52.4 22.44,51.36 C101.2@22.8,51.36
  other v1: 19.6,52.7 20.15,52.7 19.6,53.35 20.15,53.35
pads on no net: CAD1.7 CAD1.MT1 CAD1.MT2 CAD1.MT3 CAD2.6 CAD2.7 CAD2.8 CAD2.9 CAD2.MT1 CAD2.MT2 CAD2.MT3 D3.X FIDUCIAL1.1 FIDUCIAL2.1 FIDUCIAL3.1 FIDUCIAL4.1 FIDUCIAL5.1 FIDUCIAL6.1 FIDUCIAL11.1 FIDUCIAL12.1 FIDUCIAL13.1 FIDUCIAL14.1 H1.1 H2.1 H3.1 H4.1 J1.3 J1.4 J8.8 J8.9 J10.7 J11.6 J11.7 J11.8 J12.3 J12.5 J12.7 J12.17 J12.19 J12.42 J12.44 J12.45 J12.46 J12.47 J12.49 J12.51 J12.H1 J12.H2 J12.MT1 J12.MT2 J13.MNT1 J13.MNT2 J14.4 J14.8 J14.9 J14.10 J16.10 J16.11 J17.M1 J17.M2 J19.MT1 J19.MT21 J21.M1 J21.M2 J22.4 J22.MT1 J22.MT2 J24.2 J24.3 J24.4 J31.MT1 J31.MT21 J33.M1 J33.M2 P1.14 P1.H1 P1.H2 P20.4 U1.A6 U1.A16 U1.A19 U1.A20 U1.AA2 U1.AA18 U1.AA20 U1.AA21 U1.AA22 U1.AA23 U1.AB11 U1.AB12 U1.AB20 U1.AB22 U1.AC11 U1.AC21 U1.AD12 U1.AD13 U1.AD19 U1.B12 U1.B16 U1.B21 U1.C3 U1.C12 U1.C17 U1.C18 U1.C19 U1.C20 U1.C22 U1.D5 U1.D6 U1.D11 U1.D12 U1.D17 U1.D23 U1.E11 U1.E12 U1.E13 U1.E15 U1.E22 U1.E23 U1.F2 U1.F17 U1.F18 U1.F21 U1.F22 U1.G15 U1.H21 U1.J21 U1.J22 U1.J23 U1.K5 U1.L20 U1.L21 U1.M21 U1.N20 U1.N21 U1.N22 U1.N24 U1.P20 U1.P21 U1.P22 U1.P23 U1.R2 U1.R20 U1.R21 U1.T20 U1.T21 U1.T22 U1.T24 U1.U2 U1.U19 U1.U20 U1.U22 U1.V2 U1.V19 U1.V24 U1.W22 U1.W23 U1.Y2 U1.Y10 U1.Y22 U1.Y23 U8.7 U8.8 U8.15 U8.16 U8.20 U8.21 U9.6 U9.7 U9.8 U9.11 U9.15 U9.16 U9.17 U9.20 U9.21 U12.3 U12.5 U13.18 U13.19 U17.8 U17.9 U17.17 U17.19 U17.22 U17.28 U18.5 U19.5 U20.2 U20.6 U21.6

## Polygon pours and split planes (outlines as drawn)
VLDO4_2V5 on L6 PWR "Polysolid_L6" (solid, pour order 111): 28 vertices, not listed, extent 13.625,8 62.15,35.45
VSYS on L6 PWR "Polysolid_L6" (solid, remove dead copper, pour order 97): 60 vertices, not listed, extent 1.73,2.081 89.85,62.45
RGMII_1V2 on L6 PWR "Polysolid_L6" (solid, pour order 121): 21 vertices, not listed, extent 21.25,25 42.875,49
SHLD on L6 PWR "Polysolid_L6" (solid, pour order 57): 45 vertices, not listed, extent 7.125,0.25 83,13.625
PCIE_VCC on L6 PWR "Polysolid_L6" (solid, remove dead copper, pour order 95): 26 vertices, not listed, extent 15.4,16.8 67.845,58.493
5V on L6 PWR "Polysolid_L6" (solid, remove dead copper, pour order 109): 34 vertices, not listed, extent 2.7,1.75 98.65,69.5
NetC46_2 on L6 PWR "Polysolid_L6" (solid, pour order 113): 30 vertices, not listed, extent 25.875,25 40.875,39.25
NetC50_2 on L6 PWR "Polysolid_L6" (solid, pour order 115): 32 vertices, not listed, extent 28.25,25.875 37.5,37.875
NetC42_2 on L6 PWR "Polysolid_L6" (solid, pour order 117): 27.25,29.375 27.25,31.75 25.25,31.75 25.25,33.5 27.25,33.5 27.25,34.75 26.125,34.75 26.125,38.625 27.875,38.625 27.875,33.125 26,33.125 26,32.125 30.125,32.125 30.125,29.375
NetC72_2 on L6 PWR "Polysolid_L6" (solid, pour order 119): 24 vertices, not listed, extent 26.25,27.625 36.625,38.625
VLDO3_MCA on L6 PWR "Polysolid_L6" (solid, remove dead copper, pour order 125): 19 vertices, not listed, extent 5.6,16.9 92.05,64
GND on Top Layer "polysolid" (solid, remove dead copper, pour order 129): 19.6,33.3 19.6,35.35 19.75,35.5 22,35.5 22.1,35.4 22.1,34.55 22,34.45 21.288,34.45 21.038,34.2 21.038,33.388 20.85,33.2 19.7,33.2 19.6,33.3
XBEE_VCC on Top Layer "polysolid" (solid, remove dead copper, pour order 127): 20.45,53.05 20.45,53.6 20.3,53.75 16.8,53.75 16.65,53.6 16.65,52.45 16.8,52.3 20.3,52.3 20.45,52.45
RGMII_1V2 on Top Layer "Polysolid" (solid, remove dead copper, pour order 59): 31.25,39.15 31.25,43 34.142,43 34.384,42.758 34.384,39.984 33.55,39.15 31.25,39.15
SHLD on Top Layer "Polygon" (solid, pour order 61): 45 vertices, not listed, extent 7.221,0.25 83,13.5
GND on Bottom Layer "Polysolid" (solid, remove dead copper, pour order 99): 24 vertices, not listed, extent 72.95,50.8 83.675,60.15
NetL1_1 on Bottom Layer "Polysolid" (solid, remove dead copper, pour order 81): 70.7,56.15 72.65,56.15 72.75,56.25 72.75,58.85 72.65,58.95 70.85,58.95 70.7,58.8
PCIE_VCC on Bottom Layer "Polysolid" (solid, remove dead copper, pour order 79): 22 vertices, not listed, extent 65.55,49.9 70.45,61.7
GND on Bottom Layer "Polysolid" (solid, remove dead copper, pour order 123): 92.3,23.55 92.3,29.75 92.65,30.1 95.6,30.1 96,29.7 96,25.8 94.6,24.4 93.45,24.4 93.2,24.15 93.2,23.45 93.05,23.3 92.3,23.3 92.3,23.55
SHLD on Bottom Layer "Polygon" (solid, pour order 63): 45 vertices, not listed, extent 7.125,0.25 83,13.625
NetR6_2 on Bottom Layer "Polysolid" (solid, remove dead copper, pour order 67): 17 vertices, not listed, extent 85.47,17.9 91.37,21.5
VSYS on Bottom Layer "Polysolid" (solid, remove dead copper, pour order 71): 87.07,21.65 90.42,21.65 92.17,23.4 92.17,29.65 91.72,30.1 88.62,30.1 88.17,29.65 88.17,25.35 89.02,24.5 89.92,24.5 90.12,24.3 90.12,23.25 89.97,23.1 87.32,23.1 87.07,22.85
VSYS on Bottom Layer "Polysolid" (solid, remove dead copper, pour order 73): 19 vertices, not listed, extent 69.95,53.55 76.15,56
GND on Bottom Layer "Polysolid" (solid, remove dead copper, pour order 75): 41 vertices, not listed, extent 68.15,49.85 78.55,61.725
XBEE_VCC on Bottom Layer "Polysolid" (solid, remove dead copper, pour order 83): 18.45,60.95 18.45,56.9 18.3,56.75 17.1,55.55 17.1,53.7 17.1,52.85 17.8,52.15 21.6,52.15 21.85,52.4 21.85,53.75 19.85,55.75 19.85,56.25 19.85,60.9 19.75,61 18.5,61
3V3 on Bottom Layer "Polysolid" (solid, remove dead copper, pour order 85): 17.95,59.5 17.95,61.15 17.833,61.267 15.167,61.267 15.167,59.733 15.4,59.5
GND on Bottom Layer "Polysolid" (solid, remove dead copper, pour order 87): 21.465,55.09 21.465,57.465 21.85,57.85 23.6,57.85 23.6,55.09
GND on Bottom Layer "Polysolid" (solid, remove dead copper, pour order 91): 21 vertices, not listed, extent 42.85,56.6 47,63.55
PCIE_VCC on Bottom Layer "Polysolid" (solid, remove dead copper, pour order 93): 18.05,59.112 15.412,59.112 15.35,59.05 15.35,57.3 15.45,57.2 17.95,57.2 18.05,57.3 18.05,59.112
NetFIL1_1 on Bottom Layer "Polysolid" (solid, remove dead copper, pour order 105): 88.25,10.2 82.3,10.2 81.55,10.95 81.55,16.3 81.8,16.55 84.6,16.55 84.7,16.45 84.7,13.4 84.9,13.2 88.2,13.2 88.55,12.85 88.55,10.5
VIN on Bottom Layer "Polysolid" (solid, remove dead copper, pour order 107): 26 vertices, not listed, extent 83,13.45 91.85,19.35
GND on Layer 8 "Polysolid" (solid, remove dead copper, pour order 103): 20 vertices, not listed, extent 68.7,51.35 81.6,59.263
NetL1_1 on Layer 8 "Polysolid" (solid, remove dead copper, pour order 101): 80.9,55 80.9,54.1 80.25,53.45 76.3,53.45 75.8,52.95 72.25,52.95 71.9,53.3 71.9,58.35 72.15,58.6 74.75,58.6 75.35,58 75.35,56.55 75.85,56.05 80.1,56.05 80.9,55.25
GND on L2 GND (split plane): 208 vertices, not listed, extent 0.301,0.301 99.699,71.699
SHLD on L2 GND (split plane): 189 vertices, not listed, extent 7.176,0.301 82.949,15.274
GND on L4 GND (split plane): 208 vertices, not listed, extent 0.301,0.301 99.699,71.699
SHLD on L4 GND (split plane): 189 vertices, not listed, extent 7.176,0.301 82.949,15.274
AGND on L4 GND (split plane): 84 vertices, not listed, extent 65.102,4.502 76.648,28.748
3V3 on L7 3V3 (split plane): 212 vertices, not listed, extent 1.482,0.301 98.518,69.493
SHLD on L7 3V3 (split plane): 189 vertices, not listed, extent 7.176,0.301 82.949,15.274
GND on L9 GND (split plane): 208 vertices, not listed, extent 0.301,0.301 99.699,71.699
SHLD on L9 GND (split plane): 189 vertices, not listed, extent 7.176,0.301 82.949,15.274
GND on L11 GND (split plane): 208 vertices, not listed, extent 0.301,0.301 99.699,71.699
SHLD on L11 GND (split plane): 189 vertices, not listed, extent 7.176,0.301 82.949,15.274

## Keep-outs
Keep-Out Layer:
  the board outline again, w0.6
